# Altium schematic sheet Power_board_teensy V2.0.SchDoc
size 436 x 302 mm
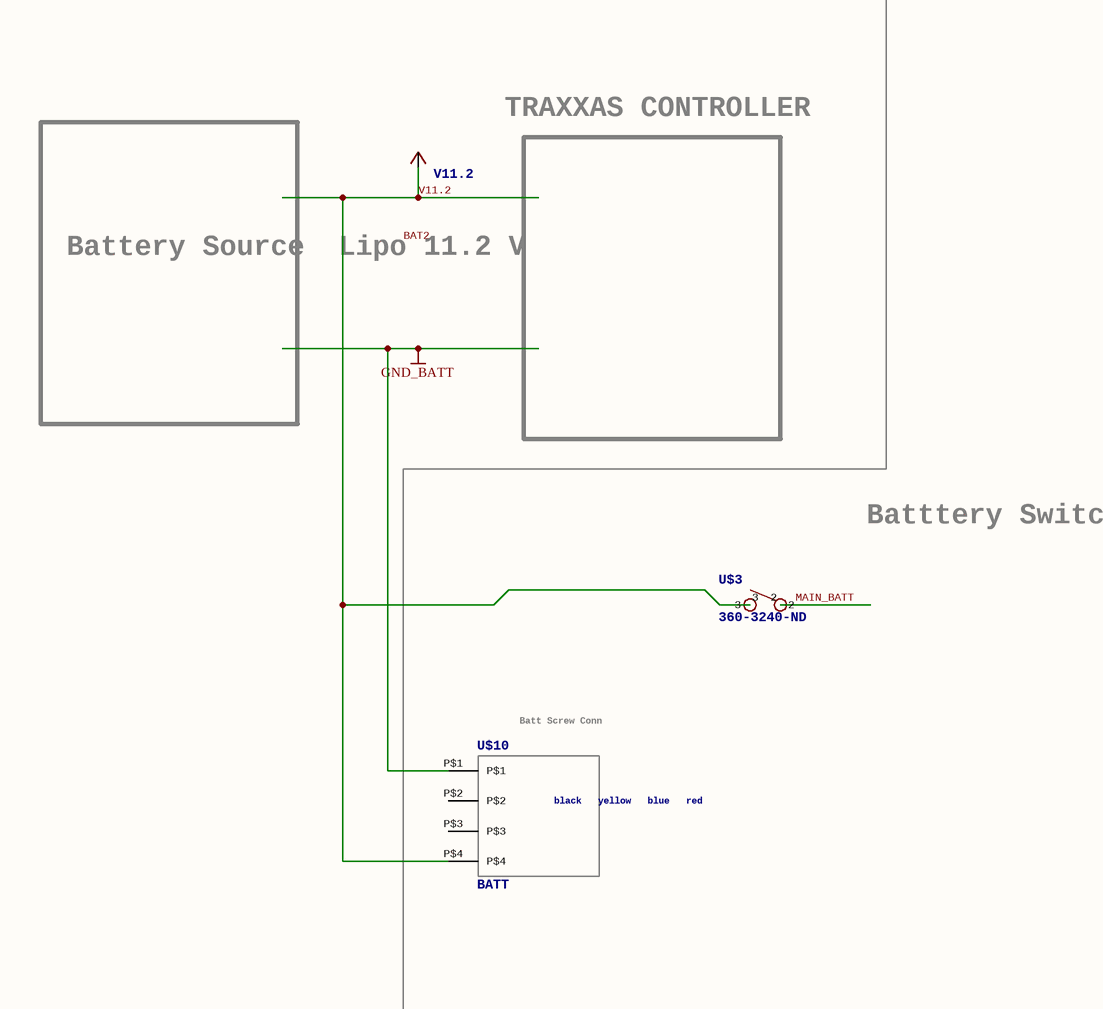
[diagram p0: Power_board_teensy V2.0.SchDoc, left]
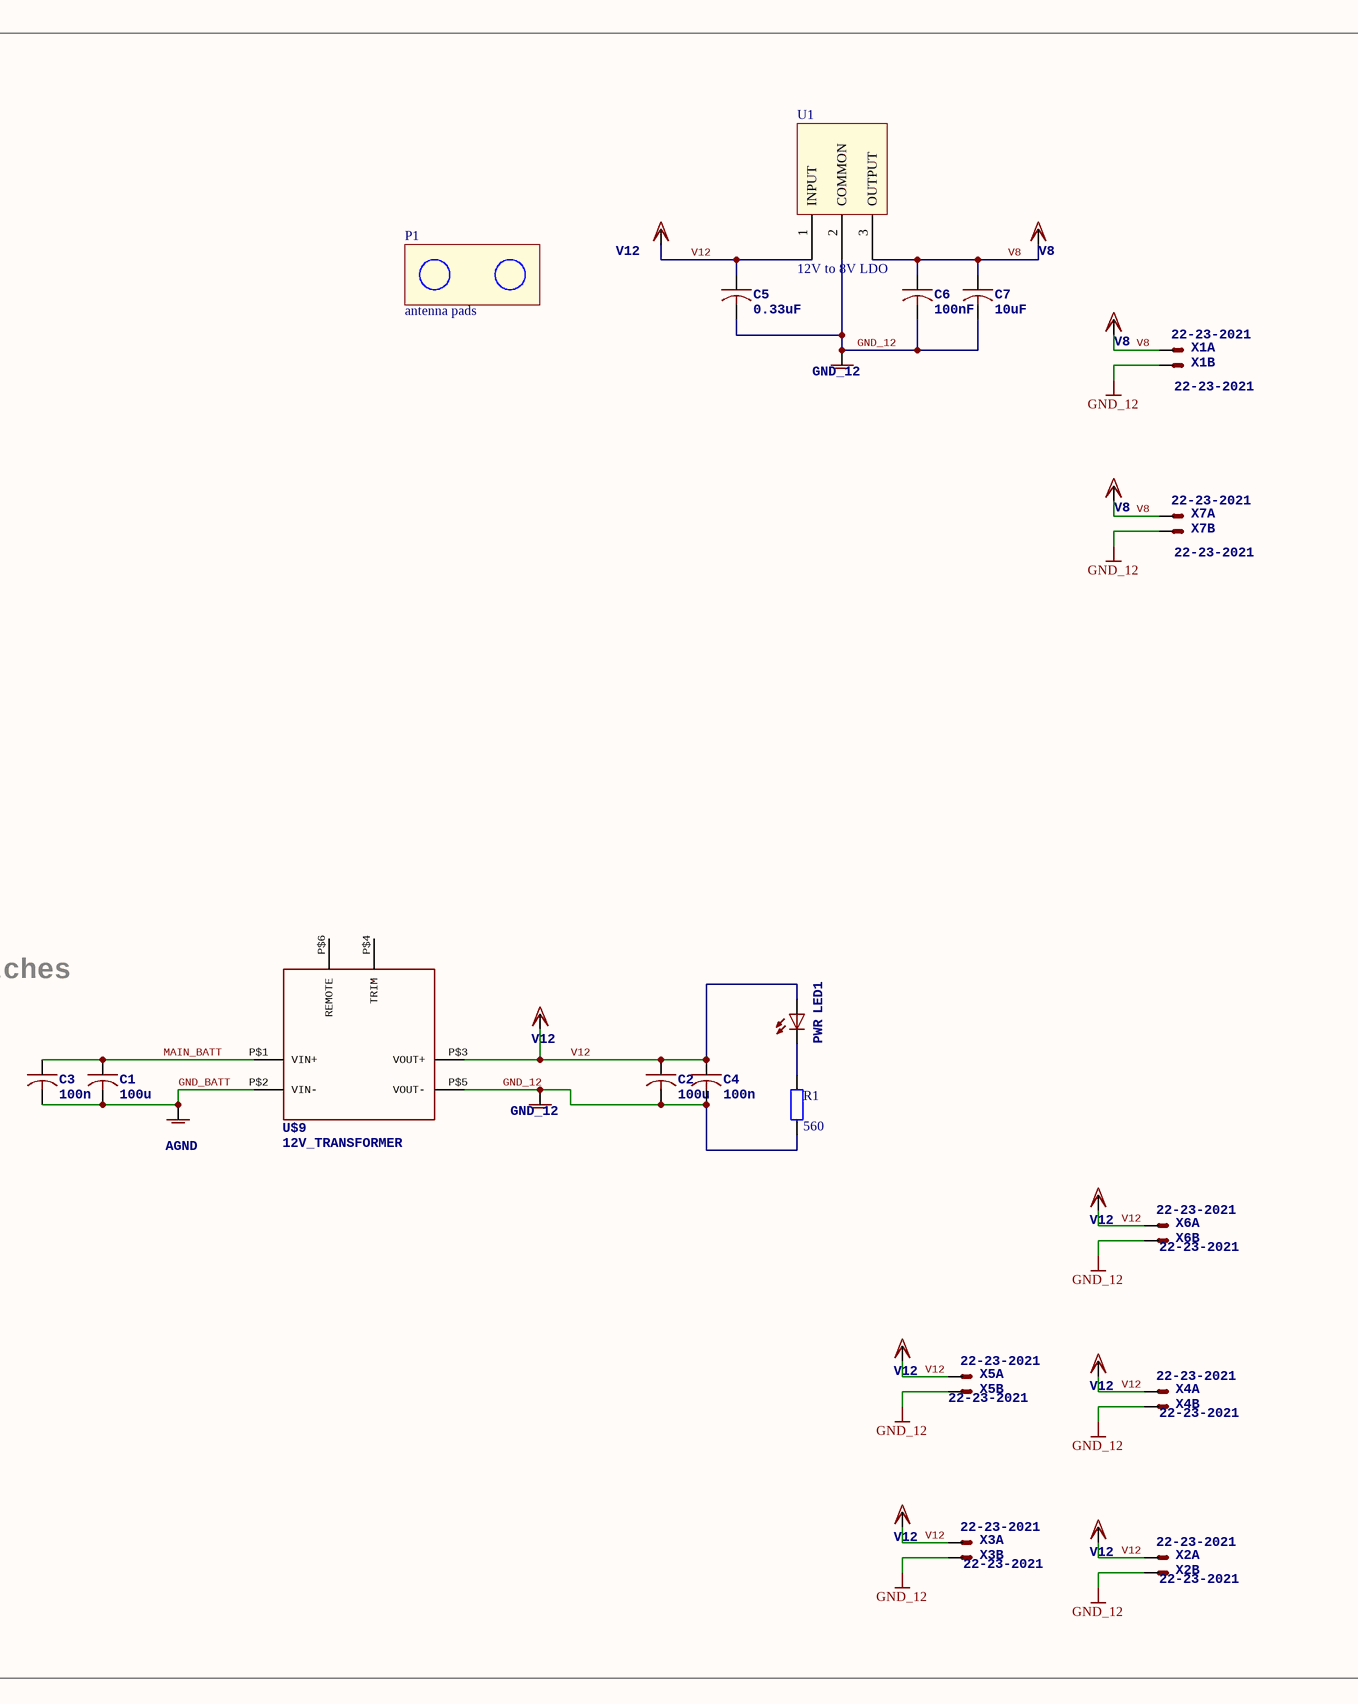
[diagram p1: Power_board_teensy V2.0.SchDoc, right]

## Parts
AGND1  GND_12
AGND2  AGND
AGND3  GND_12
C1  100u  [C050-035X075]
C2  100u  [C050-035X075]
C3  100n  [C050-035X075]
C4  100n  [C050-035X075]
C5  0.33uF  [C050-035X075]
C6  100nF  [C050-035X075]
C7  10uF  [C050-035X075]
LED1  PWR  [LED5MM]
P1  antenna pads  [Antenna pads]
R1  value 560  [AXIAL-0.4]
U1  12V to 8V LDO  [BA7808CP-E2]
U$3  360-3240-ND  [360-3240-ND]
U$9  12V_TRANSFORMER  [12V_TRANSFORMER]
U$10  BATT  black

yellow

blue

red: black / yellow / blue / red  [BATTERY_CONNECTOR]
V1  V11.2
VDD1  V12
VDD2  V8
VDD3  V8
VDD4  V8
VDD5  V12
VDD6  V12
VDD7  V12
VDD8  V12
VDD9  V12
VDD10  V12
X1  22-23-2021  [22-23-2021]  (parts A,B of 2)
X2  22-23-2021  [22-23-2021]  (parts A,B of 2)
X3  22-23-2021  [22-23-2021]  (parts A,B of 2)
X4  22-23-2021  [22-23-2021]  (parts A,B of 2)
X5  22-23-2021  [22-23-2021]  (parts A,B of 2)
X6  22-23-2021  [22-23-2021]  (parts A,B of 2)
X7  22-23-2021  [22-23-2021]  (parts A,B of 2)

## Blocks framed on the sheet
Batttery Switches: AGND1-AGND3 C1-C7 LED1 P1 R1 U1 U$3 U$9 U$10 VDD1-VDD10 X1-X7

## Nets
GND_12: AGND1.?1(AGND) AGND3.?1(AGND) C2.2 C4.2 C5.2 C6.2 C7.2 R1.1 U1.2(COMMON) U$9.P$5(VOUT-) X1.2(S) X2.2(S) X3.2(S) X4.2(S) X5.2(S) X6.2(S) X7.2(S)
GND_BATT: AGND2.?1(AGND) C1.2 C3.2 U$9.P$2(VIN-) U$10.P$1
MAIN_BATT: C1.1 C3.1 U$3.2 U$9.P$1(VIN+)
V8: C6.1 C7.1 U1.3(OUTPUT) VDD2.?1(VDD) VDD3.?1(VDD) VDD4.?1(VDD) X1.1(S) X7.1(S)
V11.2: U$3.3 U$10.P$4 V1.?1(VCC)
V12: C2.1 C4.1 C5.1 LED1.A U1.1(INPUT) U$9.P$3(VOUT+) VDD1.?1(VDD) VDD5.?1(VDD) VDD6.?1(VDD) VDD7.?1(VDD) VDD8.?1(VDD) VDD9.?1(VDD) VDD10.?1(VDD) X2.1(S) X3.1(S) X4.1(S) X5.1(S) X6.1(S)
NetLED1_K: LED1.K(C) R1.2

Not connected (* = marked no-connect by the designer): U$9 P$4(TRIM) P$6(REMOTE); U$10 P$2 P$3

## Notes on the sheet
- TRAXXAS CONTROLLER
- Battery Source
  Lipo 11.2 V
- (near U$10) Batt Screw Conn
- Labels drawn without touching a wire or pin: BAT2

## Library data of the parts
AGND1-AGND3 = AGND: SUPPLY SYMBOL
C1-C7 = C-US050-035X075: CAPACITOR, American symbol
LED1 = LED5MM
R1 = Res2: Resistor
U1 = BA78M08FP-E2
U$3 = 360-3240-ND: SPST two lead switch Pin 2 is common Swtich Closed on Down Position DigiKey: http://www.digikey.com/product-detail/en/nkk-switches/M2011S2A1W01/360-3240-ND/1049342 Data Sheet: http://2t70un3m1d9z1kztamkdrd38.wpengine.netdna-cdn.com/wp-content/uploads/2016/02/MtogglesBushing.pdf
U$9 = 12V_TRANSFORMER: CUI Inc │ SERIES: PDQ30-D │ DESCRIPTION: DC-DC CONVERTER http://www.mouser.com/pdfdocs/pdq30-d.pdf
U$10 = BATTERY_CONNECTOR
V1 = VCC: SUPPLY SYMBOL
VDD1-VDD10 = VDD: SUPPLY SYMBOL
X1-X7 = 22-23-2021: .100" (2.54mm) Center Header - 2 Pin; MF: MOLEX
